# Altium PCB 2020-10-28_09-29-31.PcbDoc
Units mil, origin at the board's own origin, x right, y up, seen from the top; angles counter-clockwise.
Board outline 3000 x 3000 mil, 4 copper layers (Top Layer, MidLayer1, MidLayer2, Bottom Layer); 24 components, 12 nets, 66 pads, 90 vias.
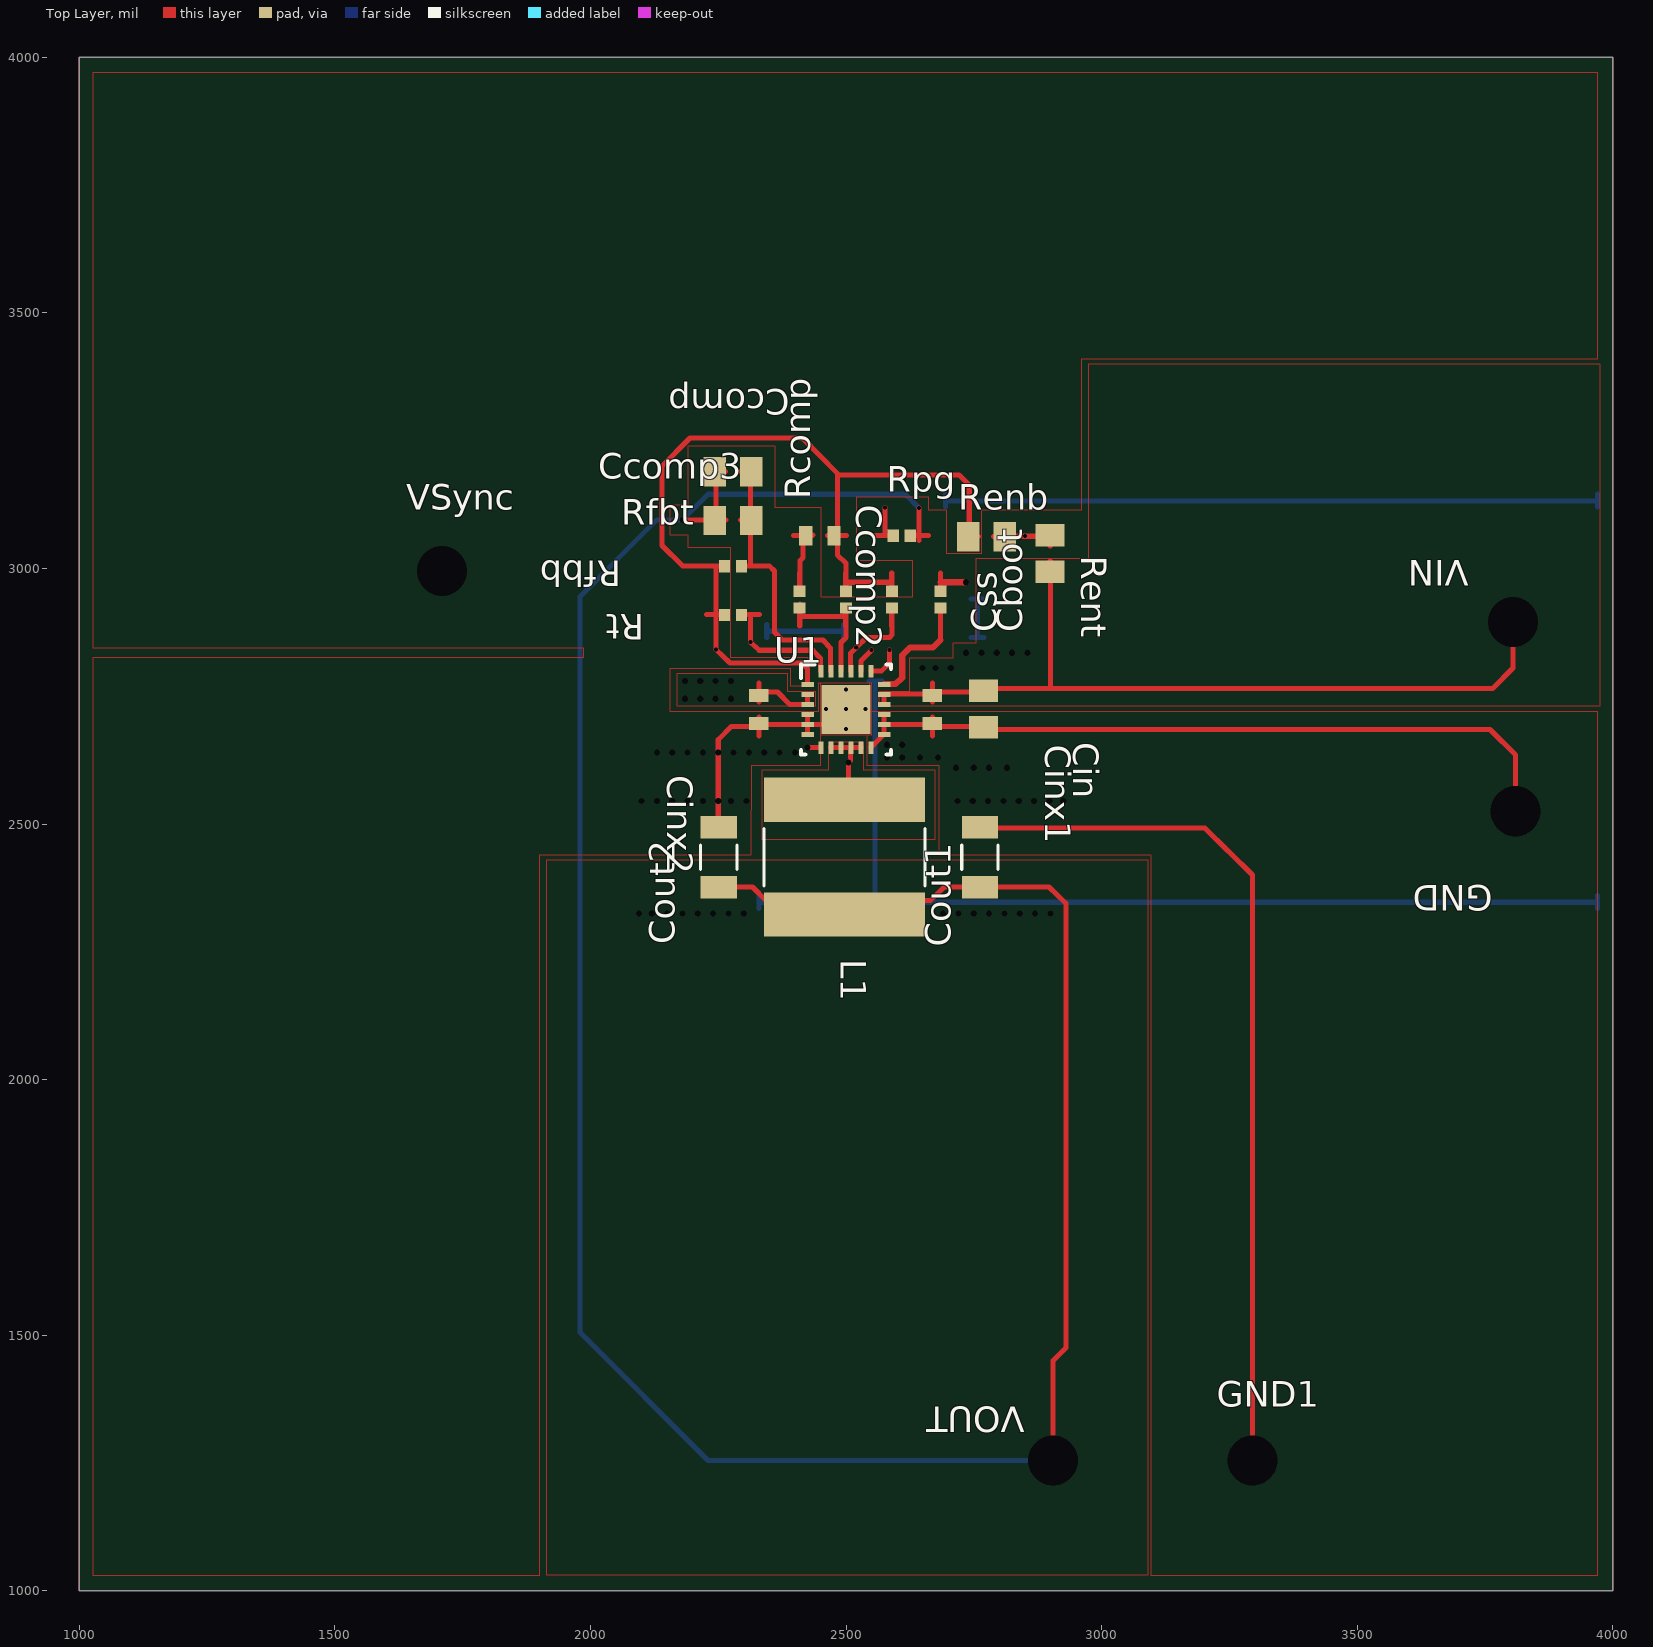
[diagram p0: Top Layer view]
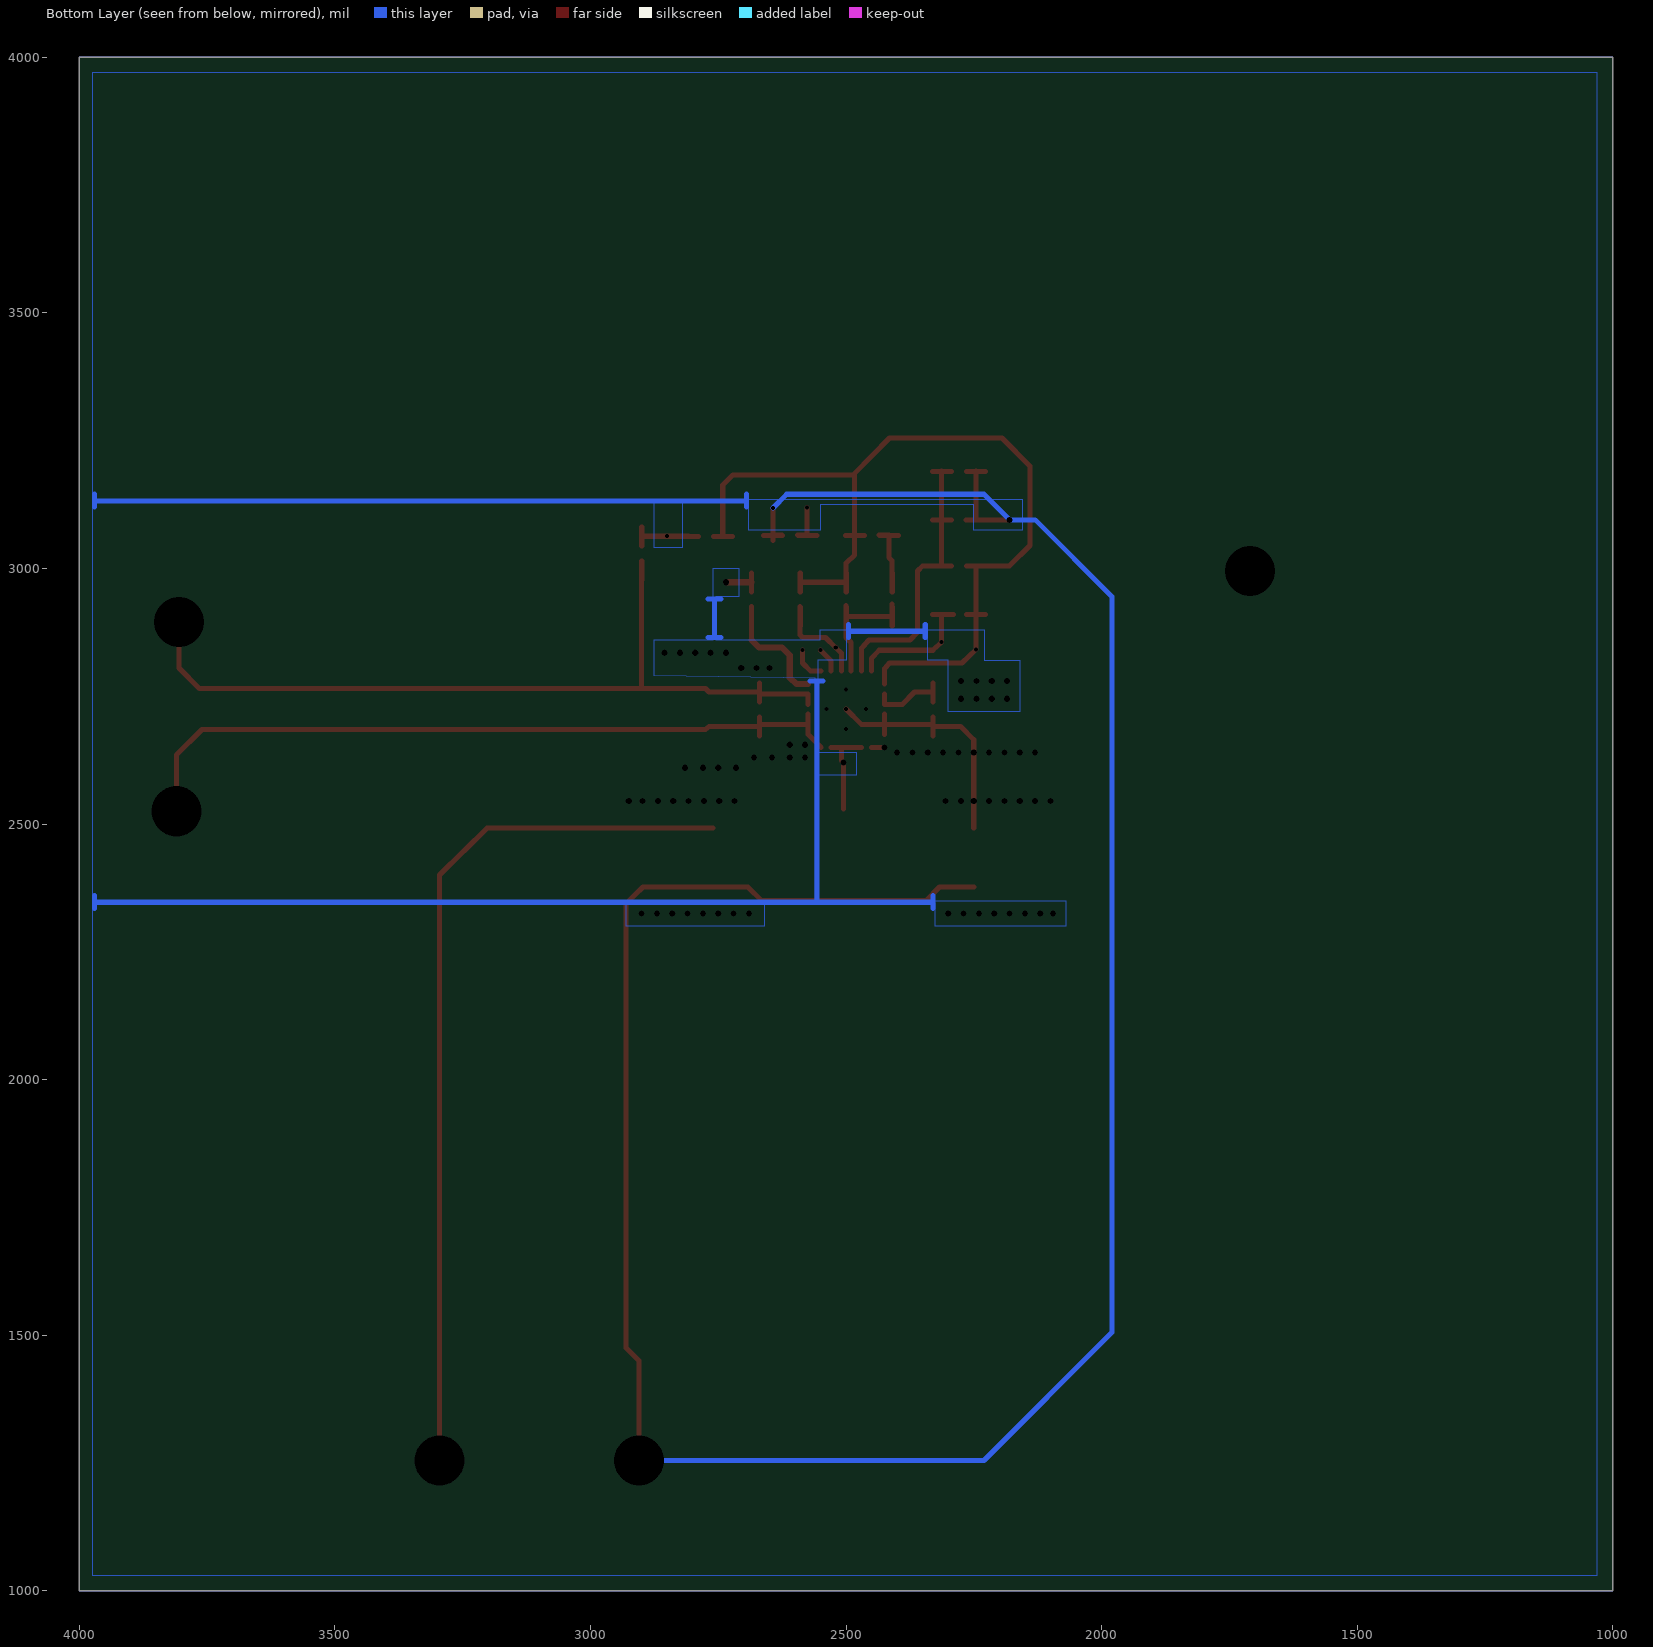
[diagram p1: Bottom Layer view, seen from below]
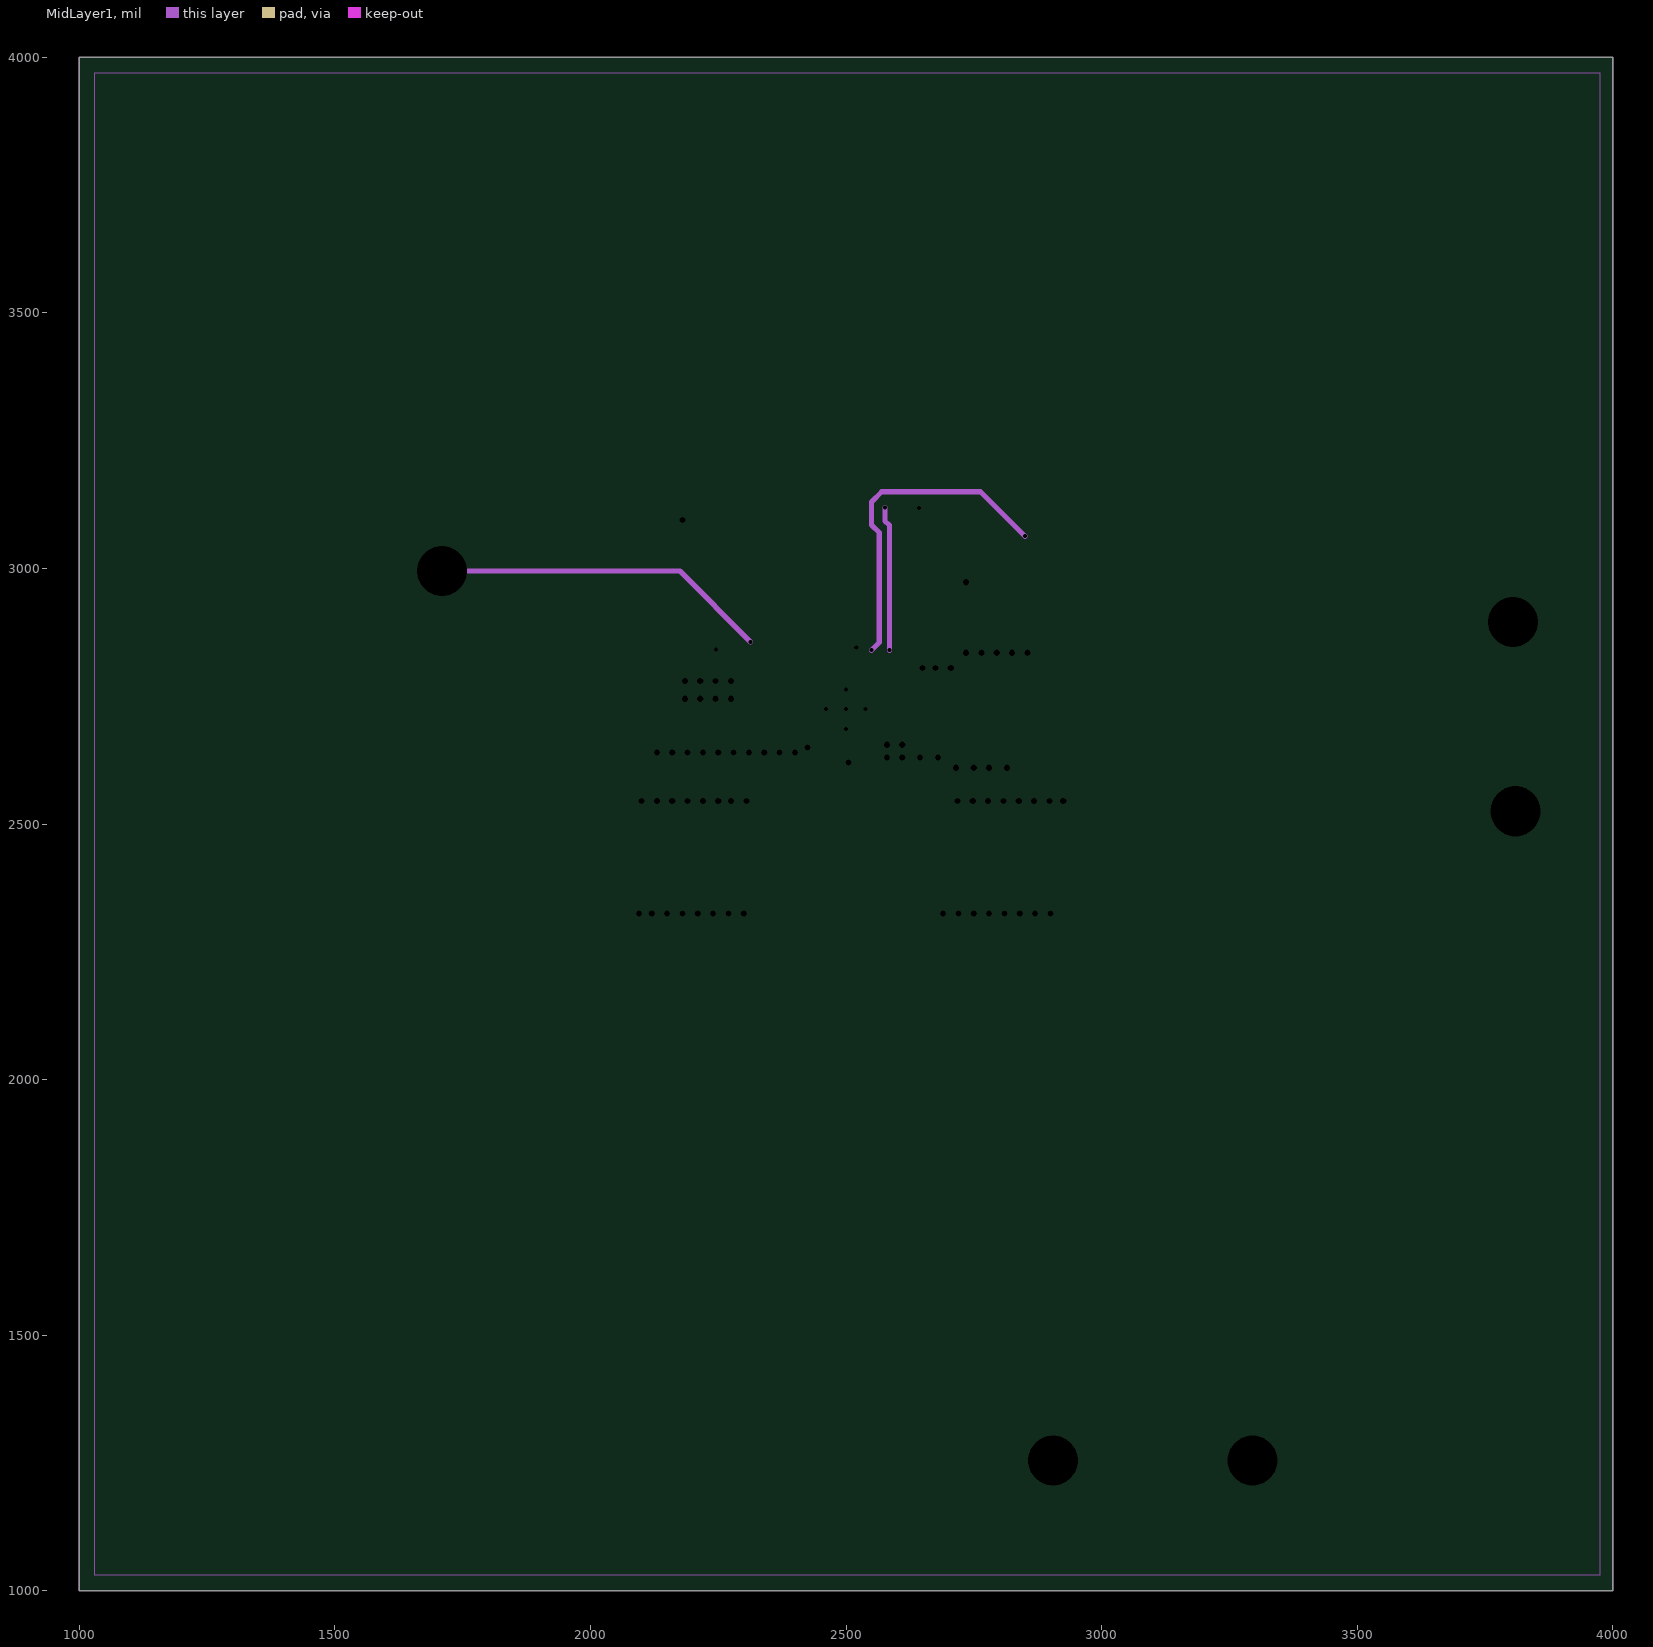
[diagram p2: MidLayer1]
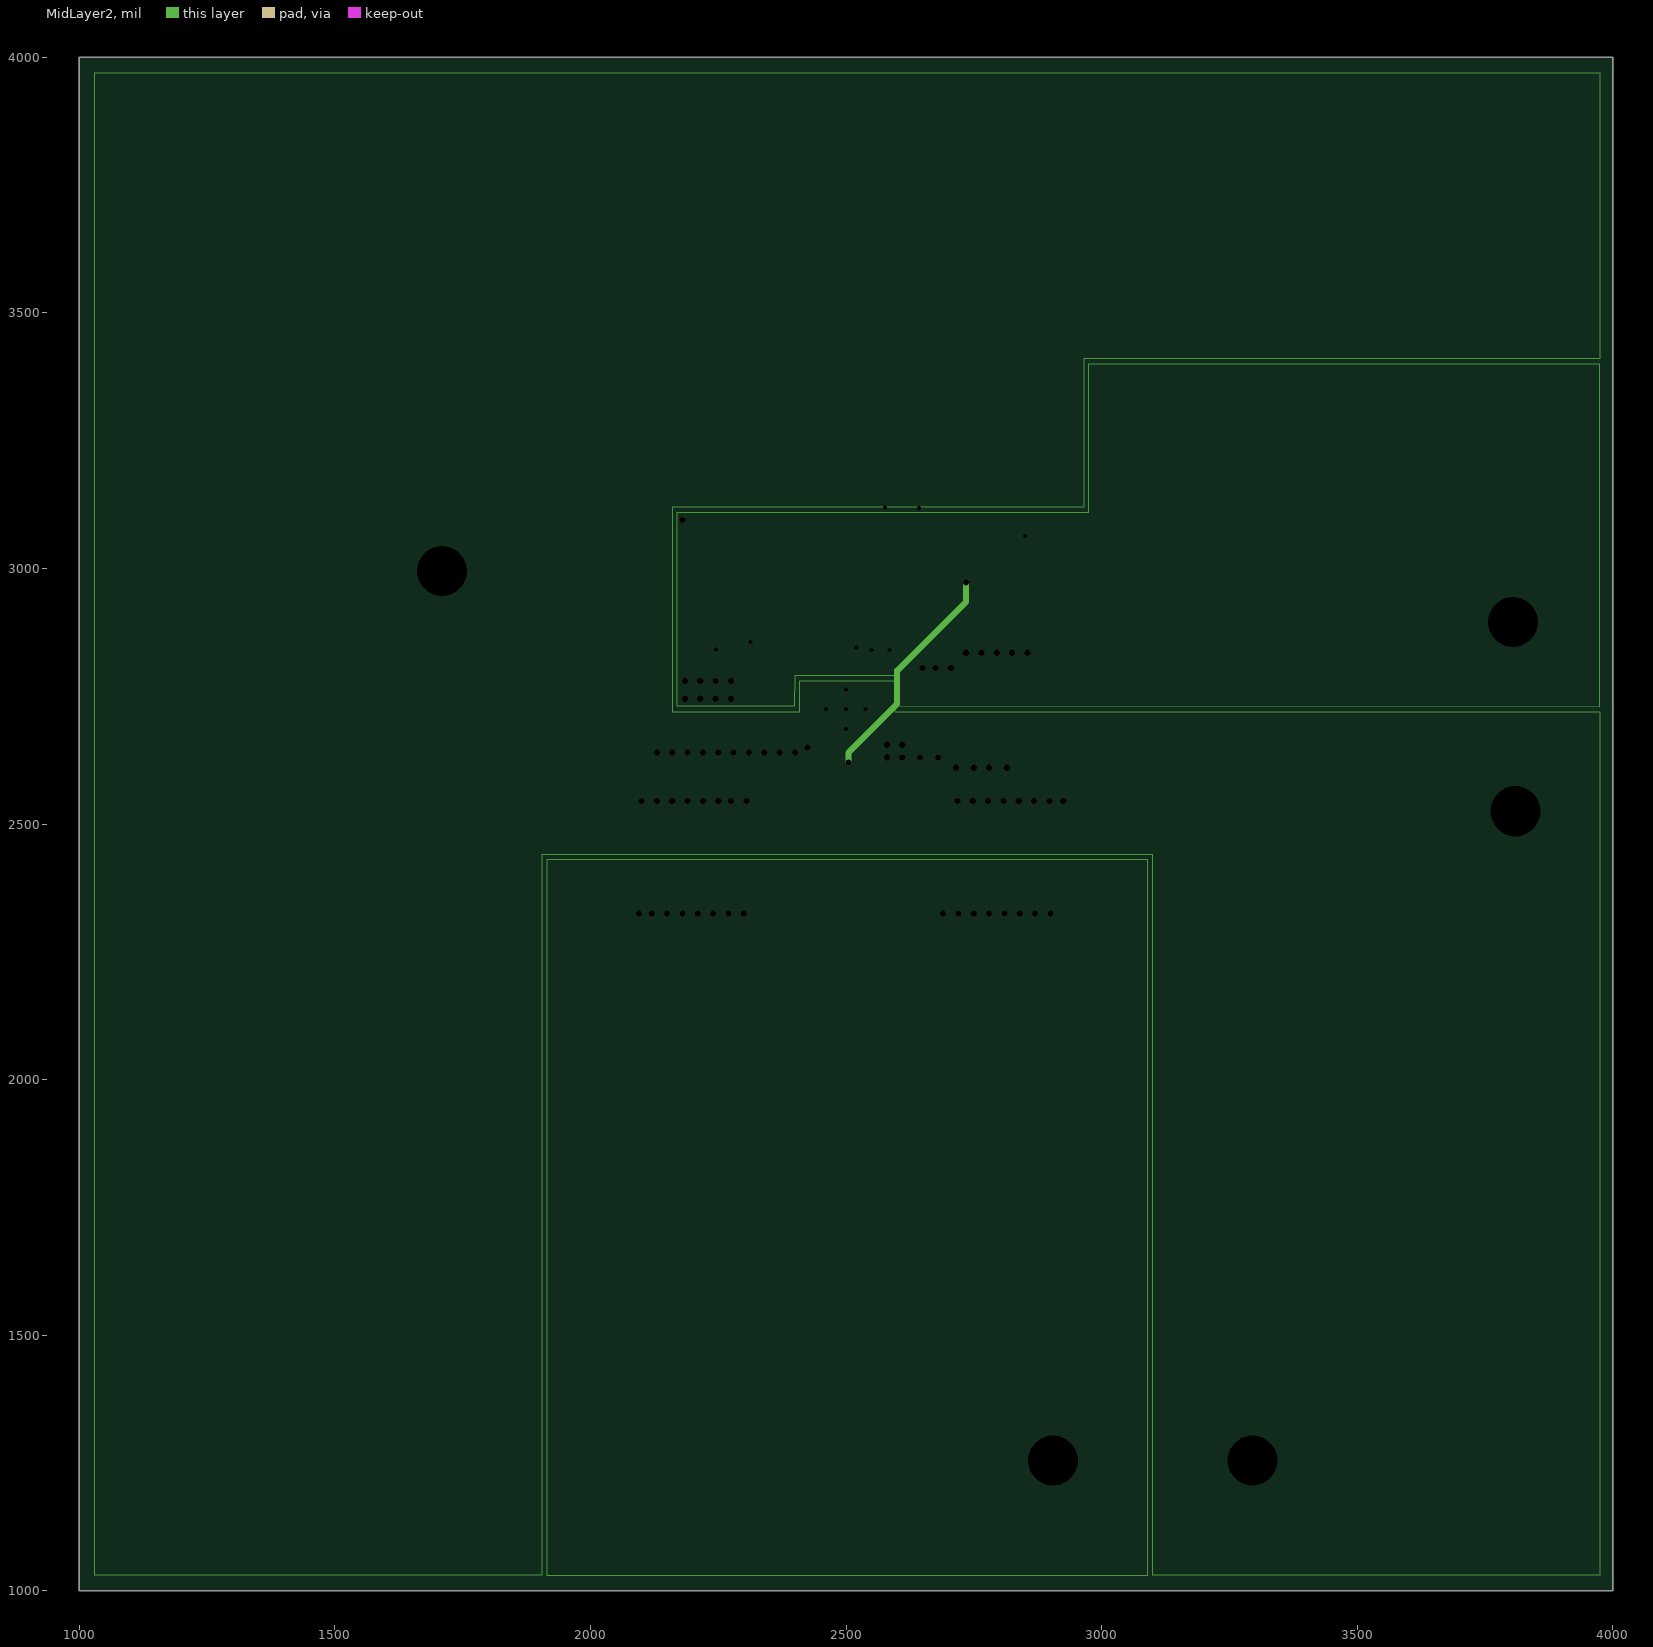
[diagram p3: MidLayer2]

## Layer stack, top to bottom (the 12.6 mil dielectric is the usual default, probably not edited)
Top Layer: signal copper 1.4
Dielectric: core 12.6, FR-4, Dk 4.8
MidLayer1: signal copper 1.4
Dielectric: prepreg 12.6, FR-4, Dk 4.8
MidLayer2: signal copper 1.4
Dielectric: core 12.6, FR-4, Dk 4.8
Bottom Layer: signal copper 1.4

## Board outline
1000,1000 4000,1000 4000,4000 1000,4000

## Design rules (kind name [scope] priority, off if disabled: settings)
PlaneConnect [All] p0: scope1count=1 scope1_0_kind=Board scope1_0_value=Board scope2count=1 scope2_0_kind=Board scope2_0_value=Board commentlength=0 planeconnectstyle=Direct reliefexpansion=20 reliefentries=4 reliefconductorwidth=10 reliefairgap=10
PlaneConnect [All] p1: planeconnectstyle=Direct reliefexpansion=20 reliefentries=4 reliefconductorwidth=10 reliefairgap=10
PolygonConnect [All] p0: scope1count=1 scope1_0_kind=Board scope1_0_value=Board scope2count=1 scope2_0_kind=Board scope2_0_value=Board commentlength=0 connectstyle=Direct reliefconductorwidth=10 reliefentries=4 polygonreliefangle="90 Angle"
PolygonConnect [All] p1: connectstyle=Direct reliefconductorwidth=10 reliefentries=4 polygonreliefangle="90 Angle"

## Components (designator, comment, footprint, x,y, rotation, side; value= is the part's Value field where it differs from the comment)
Cboot "" 0402 2685,2939 r90 top
Ccomp "" 0603 2449,3064 r180 top
Ccomp2 "" 0402 2500,2939 r270 top
Ccomp3 "" 0805 2279,3189 r0 top
Cin "" 0805 2769,2725 r270 top
Cinx1 "" 0603 2669,2724 r270 top
Cinx2 "" 0603 2329,2724 r270 top
Cout1 "" 1206_190 2762,2435 r90 top
Cout2 "" 1206_190 2251,2435 r90 top
Css "" 0402 2590,2939 r90 top
GND "" TP-1502 3809,2525 r180 top
GND1 "" TP-1502 3294,1254 r0 top
L1 "" SRN8040 2497,2435 r270 top
Rcomp "" 0402 2409,2939 r90 top
Renb "" 0805 2775,3062 r0 top
Rent "" 0805 2899,3029 r270 top
Rfbb "" 0402 2279,3004 r180 top
Rfbt "" 0805 2279,3094 r0 top
Rpg "" 0402 2609,3064 r0 top
Rt "" 0402 2279,2909 r180 top
U1 "" RTW0024B 2500,2724 r0 top
VIN "" TP-1502 3805,2894 r180 top
VOUT "" TP-1502 2905,1254 r180 top
VSync "" TP-1502 1709,2994 r0 top

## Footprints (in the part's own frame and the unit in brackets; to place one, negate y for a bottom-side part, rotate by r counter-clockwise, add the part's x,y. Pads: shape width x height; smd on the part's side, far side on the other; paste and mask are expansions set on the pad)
0402 [mil]
  rect 22x24 smd: 1(-16.5,0) 2(16.5,0)
0603 [mil]
  rect 26x38 smd: 1(-27.5,0) 2(27.5,0)
0805 [mil]
  rect 44x57 smd: 1(-35.5,0) 2(35.5,0)
1206_190 [mil]
  rect 44x71 smd: 1(-59,0) 2(59,0)
  silkscreen extent -24,-36 24,36
RTW0024B [mm]
  rect 0.6x0.24 smd: 1(-1.9,1.25) 2(-1.9,0.75) 3(-1.9,0.25) 4(-1.9,-0.25) 5(-1.9,-0.75) 6(-1.9,-1.25) 13(1.9,-1.25) 14(1.9,-0.75) 15(1.9,-0.25) 16(1.9,0.25) 17(1.9,0.75) 18(1.9,1.25)
  rect 0.24x0.6 smd: 7(-1.25,-1.9) 8(-0.75,-1.9) 9(-0.25,-1.9) 10(0.25,-1.9) 11(0.75,-1.9) 12(1.25,-1.9) 19(1.25,1.9) 20(0.75,1.9) 21(0.25,1.9) 22(-0.25,1.9) 23(-0.75,1.9) 24(-1.25,1.9)
  rect 2.45x2.45 smd: 25(0,0)
  silkscreen extent -2.22,-2.22 2.22,2.22
SRN8040 [mm]
  rect 2.2x8 smd: 1(-2.85,0) 2(2.85,0)
  silkscreen extent -1.42,-4 1.42,4
TP-1502 [mil]
  round 65 / inner round 0 / far side round 65 hole 32: 1(0,0)

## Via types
v1: diameter 0, hole 12, Top Layer to Bottom Layer, 72 vias
v2: diameter 0, hole 8, Top Layer to Bottom Layer, 13 vias
v3: diameter 0, hole 98, Top Layer to Bottom Layer, 5 vias

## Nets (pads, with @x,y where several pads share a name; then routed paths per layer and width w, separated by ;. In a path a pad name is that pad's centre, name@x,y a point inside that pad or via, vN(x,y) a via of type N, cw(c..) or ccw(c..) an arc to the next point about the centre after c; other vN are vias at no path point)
0: Ccomp2.1 Ccomp.1 Cin.2 Cinx1.2 Cinx2.2 Cout1.2 Cout2.2 Css.2 GND1.1 GND.1 Renb.1 Rfbb.2 Rt.2 U1.1 U1.4 U1.5 U1.6 U1.7 U1.12 U1.13 U1.14 U1.15 U1.25 | length 9500.2
  Top Layer w10: 2227,2909.5 Rt.2@2264,2909.5 ; 2227,3004.5 Rfbb.2@2264,3004.5 ; Cout2.2@2250,2492 v1(2250,2545) v1(2250,2640) 2250,2665 2276,2691 2330,2691 2333,2695 U1.5@2425,2695 ; 2329.5,2672 Cinx2.2@2329.5,2709 ; v1(2425,2650) U1.7@2450,2650 ; U1.6@2425,2675 U1.5@2425,2695 ; U1.4@2425,2715 U1.5@2425,2695 ; U1.1@2425,2774 2425,2804 2415,2815 2273,2815 v2(2246,2841) 2246,2910 2246,3005 2180,3005 2140,3045 2140,3200 2195,3255 2415,3255 2483,3186 ; Ccomp.1@2464,3064.5 2501,3064.5 ; Ccomp2.1@2499.5,2954 2499.5,2991 ; v2(2500,2725) 2470,2695 U1.5@2425,2695 ; U1.12@2549,2650 2574,2675 U1.14@2574,2695 ; U1.15@2574,2715 U1.14@2574,2695 ; Css.2@2589.5,2954 2589.5,2991 ; 2590,2973 2500,2973 2500,3010 2483,3026 2483,3065 2483,3183 2721,3183 2741,3163 Renb.1@2741,3063 ; 2669.5,2672 Cinx1.2@2669.5,2709 ; Renb.1@2722,3062.5 Renb.1@2759,3062.5 ; Cout1.2@2760,2492 3202,2492 3295,2400 v3(3295,1255) ; v3(3810,2525) 3810,2635 3760,2685 2775,2685 2768,2691 2670,2691 2666,2695 U1.14@2574,2695
  Bottom Layer w10: 2330,2335 2330,2347 ; 2330,2360 2330,2347 ; 2345,2865 2345,2877 ; 2345,2890 2345,2877 ; 2495,2865 2495,2877 ; 2495,2890 2495,2877 ; 2545,2780 2557,2780 ; 2557,2352 2557,2780 ; 2570,2780 2557,2780 ; 2695,3120 2695,3132 ; 2695,3145 2695,3132 ; 2745,2865 2757,2865 ; 2745,2940 2757,2940 ; 2770,2865 2757,2865 ; 2770,2940 2757,2940 ; 3970,2335 3970,2347 ; 3970,2360 3970,2347 ; 3970,3120 3970,3132 ; 3970,3145 3970,3132 ; 2330,2347 3970,2347 ; 2345,2877 2495,2877 ; 2695,3132 3970,3132 ; 2757,2865 2757,2940
  other v1: 2100,2545 2130,2545 2160,2545 2190,2545 2220,2545 2275,2545 2305,2545 2718,2545 2748,2545 2778,2545 2808,2545 2838,2545 2868,2545 2898,2545 2925,2545 2715,2610 2750,2610 2780,2610 2815,2610 2580,2630 2610,2630 2645,2630 2680,2630 2130,2640 2160,2640 2190,2640 2220,2640 2280,2640 2310,2640 2340,2640 2370,2640 2400,2640 2580,2655 2610,2655
  other v2: 2500,2686 2461,2725 2538,2725 2500,2763
1: Ccomp3.1 Cout1.1 Cout2.1 L1.1 Rfbt.1 Rpg.2 U1.8 U1.9 U1.10 U1.11 VOUT.1 | length 6148.2
  Top Layer w10: v1(2180,3095) Rfbt.1@2246,3095 ; Rfbt.1@2227,3094.5 Rfbt.1@2264,3094.5 ; Ccomp3.1@2227,3189.5 Ccomp3.1@2264,3189.5 ; Ccomp3.1@2246,3190 Rfbt.1@2246,3095 ; Cout2.1@2250,2377 2317,2377 2344,2350 2505,2350 2665,2350 2692,2377 2760,2377 2897,2377 2930,2345 2930,1475 2905,1450 v3(2905,1255) ; Rfbt.1@2265,3095 Rfbt.1@2246,3095 ; U1.8@2470,2650 2490,2650 U1.10@2509,2650 ; L1.1@2505,2529 v1(2505,2620) 2509,2624 U1.10@2509,2650 ; U1.11@2529,2650 U1.10@2509,2650 ; Rpg.2@2624,3064.5 2661,3064.5 ; Rpg.2@2625,3065 2643,3065 ; 2643,3055 2643,3065 ; v2(2643,3118) 2643,3065 ; 2684.5,2954 2684.5,2991 ; 2685,2955 2685,2973
  Top Layer w12: 2685,2973 v1(2735,2973)
  MidLayer2 w12: v1(2505,2620) 2505,2640 2600,2735 2600,2800 2735,2935 v1(2735,2973)
  Bottom Layer w10: v2(2643,3118) 2616,3145 2230,3145 v1(2180,3095) 2130,3095 1980,2945 1980,1505 2230,1255 v3(2905,1255)
  other v1: 2095,2325 2120,2325 2150,2325 2180,2325 2210,2325 2240,2325 2270,2325 2300,2325 2690,2325 2720,2325 2750,2325 2780,2325 2810,2325 2840,2325 2870,2325 2900,2325
3: Ccomp3.2 Rfbb.1 Rfbt.2 U1.23 | length 671.3
  Top Layer w10: Rfbb.1@2294,3004.5 2331,3004.5 ; Rfbt.2@2294,3094.5 Rfbt.2@2331,3094.5 ; Ccomp3.2@2294,3189.5 Ccomp3.2@2331,3189.5 ; Rfbb.1@2295,3005 2313,3005 ; Rfbt.2@2295,3095 Rfbt.2@2313,3095 ; Ccomp3.2@2313,3190 Rfbt.2@2313,3095 ; U1.23@2470,2799 2470,2844 2455,2860 2375,2860 2360,2875 2360,2995 2350,3005 2313,3005 ; 2313,3005 Rfbt.2@2313,3095
6: Ccomp2.2 Rcomp.1 U1.22 | length 320.1
  Top Layer w10: 2409.5,2887 Rcomp.1@2409.5,2924 ; Rcomp.1@2410,2930 2410,2906 2500,2906 ; U1.22@2490,2799 2490,2855 2500,2865 2500,2906 ; 2499.5,2887 Ccomp2.2@2499.5,2924 ; Ccomp2.2@2500,2927 2500,2906
7: Cboot.2 L1.2
8: Ccomp.2 Rcomp.2 | length 205.5
  Top Layer w10: 2397,3064.5 Ccomp.2@2434,3064.5 ; Rcomp.2@2409.5,2954 2409.5,2991 ; Rcomp.2@2410,2955 2410,2973 2410,3015 2416,3021 2416,3065 2435,3065
9: Cin.1 Cinx1.1 Cinx2.1 Rent.2 U1.2 U1.3 U1.16 U1.17 VIN.1 | length 1829.1
  Top Layer w10: Cinx2.1@2329.5,2739 2329.5,2776 ; Cinx2.1@2330,2758 2366,2758 2390,2734 2425,2734 U1.2@2425,2754 ; U1.16@2574,2734 2574,2754 2666,2754 2670,2758 2768,2758 2775,2765 2900,2765 ; Cinx1.1@2669.5,2739 2669.5,2776 ; Rent.2@2899.5,2977 Rent.2@2899.5,3014 ; Rent.2@2900,2996 2900,2765 ; v3(3805,2895) 3805,2805 3765,2765 2900,2765
  other v1: 2185,2745 2215,2745 2245,2745 2275,2745 2185,2780 2215,2780 2245,2780 2275,2780 2650,2805 2675,2805 2705,2805 2735,2835 2765,2835 2795,2835 2825,2835 2855,2835
14: Rt.1 U1.24 VSync.1 | length 950.1
  Top Layer w10: Rt.1@2290,2910 2313,2910 v2(2313,2856) 2330,2840 2435,2840 2450,2824 U1.24@2450,2799 ; Rt.1@2294,2909.5 2331,2909.5
  MidLayer1 w10: v3(1710,2995) 2175,2995 v2(2313,2856)
15: Rpg.1 U1.19 | length 460.7
  Top Layer w10: U1.19@2549,2799 2569,2799 2585,2815 v2(2585,2840) ; 2557,3064.5 Rpg.1@2594,3064.5 ; v2(2576,3119) 2576,3065 Rpg.1@2595,3065
  MidLayer1 w10: v2(2576,3119) 2576,3093 2585,3085 v2(2585,2840)
16: Cboot.1 U1.18 | length 274.1
  Top Layer w10: 2684.5,2887 Cboot.1@2684.5,2924 ; 2685,2860 2685,2906 Cboot.1@2685,2925
  Top Layer w12: U1.18@2574,2774 2597,2774 2610,2786 2610,2830 2625,2845 2670,2845 2685,2860
18: Renb.2 Rent.1 U1.20 | length 862.4
  Top Layer w10: U1.20@2529,2799 2529,2819 v2(2550,2840) ; Renb.2@2789,3062.5 Renb.2@2826,3062.5 ; Renb.2@2808,3063 v2(2850,3063) Rent.1@2900,3063 ; Rent.1@2899.5,3044 Rent.1@2899.5,3081
  MidLayer1 w10: v2(2550,2840) 2565,2855 2565,3070 2550,3085 2550,3130 2570,3150 2763,3150 v2(2850,3063)
21: Css.1 U1.21 | length 222.9
  Top Layer w10: U1.21@2509,2799 2509,2834 v2(2520,2845) 2540,2865 2585,2865 2590,2870 2590,2906 Css.1@2590,2925 ; 2589.5,2887 Css.1@2589.5,2924

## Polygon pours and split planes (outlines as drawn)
0 on Bottom Layer " " (solid, pour order 6): 2710,2945 2755,2945 2755,2860 2550,2860 2550,2880 2230,2880 2230,2820 2160,2820 2160,2720 2300,2720 2300,2820 2340,2820 2340,2875 2500,2875 2500,2820 2555,2820 2555,2640 2480,2640 2480,2595 2555,2595 2555,2350 2070,2350 2070,2300 2325,2300 2325,2345 2660,2345 2660,2300 2930,2300 2930,2345 3975,2345 3975,1030 1030,1030 1030,3970 3975,3970 3975,3135 2155,3135 2155,3075 2250,3075 2250,3125 2550,3125 2550,3075 2690,3075 2690,3130 2820,3130 2820,3040 2875,3040 2875,3130 3975,3130 3975,2350 2560,2350 2560,2785 2875,2790 2875,2860 2760,2860 2760,3000 2710,3000
9 on Top Layer " " (solid, pour order 0): 2385,2760 2440,2760 2440,2730 2395,2730 2170,2730 2170,2795 2385,2795
1 on Top Layer " " (solid, pour order 1): 2535,2660 2465,2660 2465,2605 2335,2605 2335,2470 2675,2470 2675,2605 2535,2605
9 on Top Layer " " (solid, pour order 2): 2710,2825 2710,2855 2755,2855 2755,3020 2975,3020 2975,3400 3975,3400 3975,2730 2600,2730 2565,2730 2565,2760 2625,2760 2625,2825
1 on Top Layer " " (solid, pour order 3): 1915,2430 3090,2430 3090,1030 1915,1030
0 on Top Layer " " (solid, pour order 7): 2450,2775 2450,2675 2550,2675 2550,2775
0 on Top Layer " " (solid, pour order 8): 2696,3115 2696,3030 2766,3030 2766,3115 2961,3115 2961,3410 3971,3410 3971,3970 1026,3970 1026,2845 1986,2845 1986,2825 1026,2825 1026,1030 1901,1030 1901,2440 2315,2440 2316,2615 2451,2615 2451,2675 2541,2675 2541,2615 2681,2615 2681,2440 3096,2440 3096,1030 3971,1030 3971,2720 2546,2720 2546,2775 2446,2775 2446,2720 2156,2720 2156,2805 2391,2805 2391,2770 2426,2770 2426,2825 2275,2825 2275,3040 2191,3040 2191,3065 2156,3065 2156,3125 2191,3125 2191,3240 2361,3240 2361,3120 2451,3120 2451,2945 2631,2945 2631,3015 2521,3015 2521,3140 2661,3140 2661,3115
9 on MidLayer2 " " (solid, pour order 4): 2975,3110 2975,3400 3974,3400 3974,2729 2595,2730 2595,2790 2400,2790 2399,2730 2170,2730 2170,3110
1 on MidLayer2 " " (solid, pour order 5): 3090,2430 1915,2430 1915,1030 3090,1030
0 on MidLayer1 " " (solid, pour order 9): 3975,1030 1030,1030 1030,3970 3975,3970
0 on MidLayer2 " " (solid, pour order 10): 3975,1030 3100,1030 3100,2440 1905,2440 1905,1030 1030,1030 1030,3970 3975,3970 3975,3410 2965,3410 2965,3120 2160,3120 2160,2720 2410,2720 2410,2780 2595,2780 2595,2720 3975,2720

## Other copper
Multi-Layer:
  the board outline again, w1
